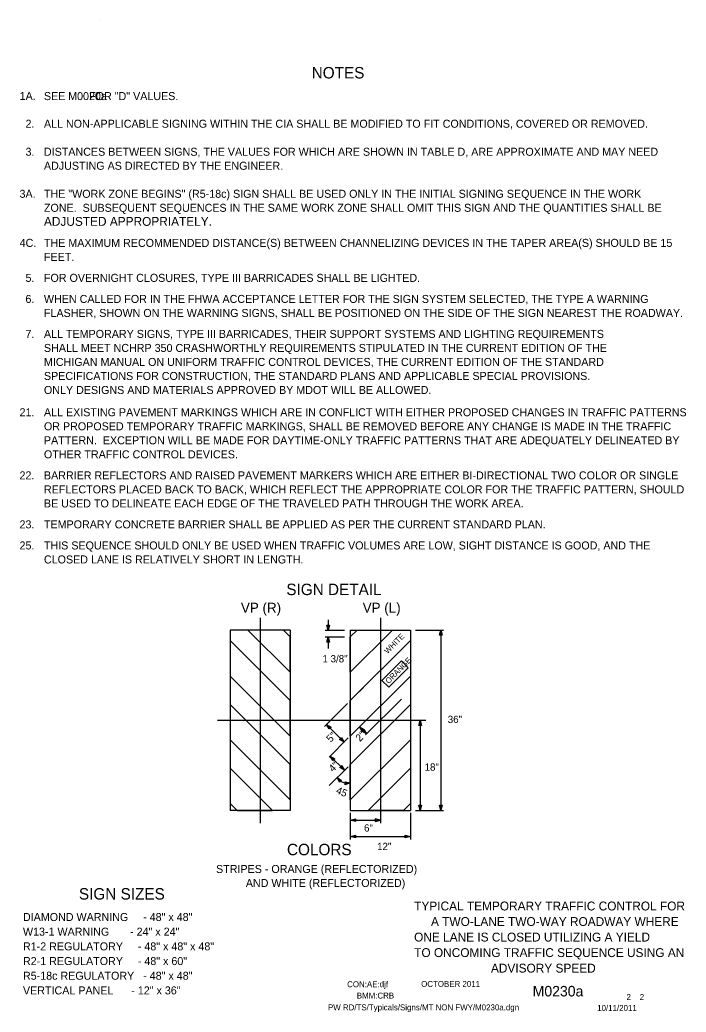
# Model space of a CAD drawing. Extents: x 16768 to 18475, y 7218 to 8259.
# Drawn here: x 17776 to 18475, y 7218 to 8259 of the extents above; entities that cross this region are included whole.
import ezdxf

# ---------------------------------------------------------------- set-up
doc = ezdxf.new("R2010")
doc.units = 0
for name, color, linetype in [('BORDER', 7, 'Continuous'), ('BORDER_SIGNAL_WO', 7, 'Continuous'), ('TRAFFIC_SIGNS_PR', 7, 'Continuous'), ('TYPICAL_TEXT_DIMEN_PR', 7, 'Continuous')]:
    doc.layers.add(name, color=color, linetype=linetype)

msp = doc.modelspace()

# ---------------------------------------------------------------- linework, layer by layer
at = {"layer": 'BORDER'}
msp.add_line((17859.8, 8259.1), (17859.8, 8259.1), dxfattribs=at)
at = {"layer": 'TRAFFIC_SIGNS_PR'}
for p, q in [((18059.9, 7618.8), (17996.9, 7618.8)), ((17996.9, 7618.8), (17996.9, 7429.8)), ((18059.9, 7574.6), (18015.7, 7618.8)), ((18059.9, 7611.7), (18052.8, 7618.8)), ((18059.9, 7618.8), (18059.9, 7429.8)), ((18123, 7618.8), (18186, 7618.8)), ((18123, 7618.8), (18123, 7429.8)), ((18123, 7611.7), (18130.1, 7618.8)), ((18123, 7574.6), (18167.2, 7618.8)), ((18186, 7618.8), (18186, 7429.8)), ((18059.9, 7544.9), (17996.9, 7607.9)), ((18123, 7544.9), (18186, 7607.9)), ((18059.9, 7507.7), (17996.9, 7570.7)), ((18123, 7507.7), (18186, 7570.7)), ((18132.3, 7554.1), (18141.5, 7563.4)), ((18059.9, 7478), (17996.9, 7541)), ((18123, 7478), (18186, 7541)), ((18059.9, 7440.9), (17996.9, 7503.9)), ((18123, 7440.9), (18186, 7503.9)), ((18041.3, 7429.8), (17996.9, 7474.2)), ((18141.6, 7429.8), (18186, 7474.2)), ((18004.2, 7429.8), (17996.9, 7437.1)), ((18178.7, 7429.8), (18186, 7437.1)), ((18059.9, 7429.8), (17996.9, 7429.8)), ((18123, 7429.8), (18186, 7429.8))]:
    msp.add_line(p, q, dxfattribs=at)
for points in [[(18052.8, 7618.8), (18015.7, 7618.8), (18059.9, 7574.6), (18059.9, 7611.7)], [(18130.1, 7618.8), (18167.2, 7618.8), (18123, 7574.6), (18123, 7611.7)], [(18059.9, 7544.9), (17996.9, 7607.9), (17996.9, 7570.7), (18059.9, 7507.7)], [(18123, 7544.9), (18186, 7607.9), (18186, 7570.7), (18123, 7507.7)], [(18059.9, 7478), (17996.9, 7541), (17996.9, 7503.9), (18059.9, 7440.9)], [(18123, 7478), (18186, 7541), (18186, 7503.9), (18123, 7440.9)], [(17996.9, 7474.2), (17996.9, 7437.1), (18004.2, 7429.8), (18041.3, 7429.8)], [(18186, 7474.2), (18186, 7437.1), (18178.7, 7429.8), (18141.6, 7429.8)]]:
    msp.add_lwpolyline(points, close=True, dxfattribs=at)
at = {"layer": 'TYPICAL_TEXT_DIMEN_PR'}
for p, q in [((18028.4, 7631.9), (18028.4, 7416.4)), ((18154.5, 7631.9), (18154.5, 7416.4)), ((18099.9, 7618.8), (18098.4, 7624.2)), ((18098.4, 7624.2), (18099.9, 7624.2)), ((18099.9, 7629.7), (18099.9, 7618.8)), ((18099.9, 7624.2), (18101.3, 7624.2)), ((18101.3, 7624.2), (18099.9, 7618.8)), ((18096.7, 7618.8), (18116.9, 7618.8)), ((18096.7, 7611.7), (18116.9, 7611.7)), ((18098.4, 7606.3), (18099.9, 7611.7)), ((18099.9, 7611.7), (18099.9, 7599.6)), ((18099.9, 7611.7), (18101.3, 7606.3)), ((18191.3, 7618.8), (18220.8, 7618.8)), ((18216.4, 7613.4), (18217.8, 7618.8)), ((18217.8, 7613.4), (18216.4, 7613.4)), ((18217.8, 7618.8), (18217.8, 7429.8)), ((18217.8, 7618.8), (18219.3, 7613.4)), ((18219.3, 7613.4), (18217.8, 7613.4)), ((18099.9, 7606.3), (18098.4, 7606.3)), ((18101.3, 7606.3), (18099.9, 7606.3)), ((18095.9, 7517.7), (18120, 7541.9)), ((18139, 7508.9), (18176.7, 7546.6)), ((17983.8, 7524.3), (18202.2, 7524.3)), ((18116.7, 7501.4), (18098.1, 7520)), ((18100.9, 7515.2), (18098.1, 7520)), ((18098.1, 7520), (18102.9, 7517.2)), ((18101.9, 7516.2), (18100.9, 7515.2)), ((18102.9, 7517.2), (18101.9, 7516.2)), ((18140.1, 7509.9), (18132.6, 7517.4)), ((18135.4, 7512.5), (18132.6, 7517.4)), ((18132.6, 7517.4), (18137.4, 7514.6)), ((18194.7, 7518.9), (18196.2, 7524.3)), ((18196.2, 7518.9), (18194.7, 7518.9)), ((18196.2, 7524.3), (18196.2, 7429.8)), ((18196.2, 7524.3), (18197.6, 7518.9)), ((18197.6, 7518.9), (18196.2, 7518.9)), ((18100.7, 7485.5), (18120.9, 7505.7)), ((18112.9, 7505.2), (18113.9, 7506.3)), ((18113.9, 7506.3), (18116.7, 7501.4)), ((18135.2, 7512.7), (18136.2, 7513.7)), ((18140.1, 7509.9), (18135.2, 7512.7)), ((18136.4, 7513.5), (18135.4, 7512.5)), ((18136.2, 7513.7), (18137.3, 7514.7)), ((18137.4, 7514.6), (18136.4, 7513.5)), ((18137.3, 7514.7), (18140.1, 7509.9)), ((18111.8, 7504.2), (18112.9, 7505.2)), ((18116.7, 7501.4), (18111.8, 7504.2)), ((18116.9, 7471.9), (18102, 7486.8)), ((18104.8, 7482), (18102, 7486.8)), ((18102, 7486.8), (18106.9, 7484)), ((18100.7, 7455.8), (18120.6, 7475.6)), ((18105.8, 7483), (18104.8, 7482)), ((18106.9, 7484), (18105.8, 7483)), ((18112, 7474.7), (18113.1, 7475.7)), ((18116.9, 7471.9), (18112, 7474.7)), ((18113.1, 7475.7), (18114.1, 7476.8)), ((18114.1, 7476.8), (18116.9, 7471.9)), ((18111.6, 7459.2), (18109.2, 7464.2)), ((18109.2, 7464.2), (18113.8, 7461.1)), ((18112.7, 7460.1), (18111.6, 7459.2)), ((18113.8, 7461.1), (18112.7, 7460.1)), ((18117.6, 7458.2), (18117.5, 7459.6)), ((18117.5, 7459.6), (18123, 7458.5)), ((18117.7, 7456.7), (18117.6, 7458.2)), ((18123, 7458.5), (18117.7, 7456.7)), ((18196.2, 7429.8), (18194.7, 7435.2)), ((18194.7, 7435.2), (18196.2, 7435.2)), ((18196.2, 7435.2), (18197.6, 7435.2)), ((18197.6, 7435.2), (18196.2, 7429.8)), ((18217.8, 7429.8), (18216.4, 7435.2)), ((18216.4, 7435.2), (18217.8, 7435.2)), ((18217.8, 7435.2), (18219.3, 7435.2)), ((18219.3, 7435.2), (18217.8, 7429.8)), ((18123, 7427.2), (18123, 7399.2)), ((18186, 7427.2), (18186, 7399.2)), ((18191.3, 7429.8), (18220.8, 7429.8)), ((18123, 7419.6), (18128.4, 7421)), ((18123, 7419.6), (18154.5, 7419.6)), ((18128.4, 7418.1), (18123, 7419.6)), ((18128.4, 7421), (18128.4, 7419.6)), ((18128.4, 7419.6), (18128.4, 7418.1)), ((18154.5, 7419.6), (18149.1, 7421)), ((18149.1, 7421), (18149.1, 7419.6)), ((18149.1, 7419.6), (18149.1, 7418.1)), ((18149.1, 7418.1), (18154.5, 7419.6)), ((18123, 7402.4), (18128.4, 7403.8)), ((18123, 7402.4), (18186, 7402.4)), ((18128.4, 7401), (18123, 7402.4)), ((18128.4, 7403.8), (18128.4, 7402.4)), ((18128.4, 7402.4), (18128.4, 7401)), ((18180.6, 7402.4), (18180.6, 7403.8)), ((18180.6, 7403.8), (18186, 7402.4)), ((18186, 7402.4), (18180.6, 7401)), ((18180.6, 7401), (18180.6, 7402.4))]:
    msp.add_line(p, q, dxfattribs=at)
msp.add_lwpolyline([(18156.1, 7566.1), (18176.6, 7586.5), (18183.7, 7579.3), (18163.3, 7558.9)], close=True, dxfattribs=at)
msp.add_arc((18120.2, 7471.4), 13.1, 212.8393, 282.1565, dxfattribs=at)

# ---------------------------------------------------------------- texts
at = {"layer": 'BORDER'}
for s, p in [('TYPICAL TEMPORARY TRAFFIC CONTROL FOR', (18190, 7324.8)), ('A TWO-LANE TWO-WAY ROADWAY WHERE', (18207.6, 7308.5)), ('ONE LANE IS CLOSED UTILIZING A YIELD ', (18189.9, 7292.2)), ('TO ONCOMING TRAFFIC SEQUENCE USING AN', (18190, 7275.9)), ('ADVISORY SPEED', (18270.5, 7259.6))]:
    msp.add_text(s, height=9.3, dxfattribs=at).set_placement(p)
at = {"layer": 'BORDER_SIGNAL_WO'}
for s, height, p in [('CON:AE:djf', 6.2, (18119.7, 7244.3)), ('    OCTOBER 2011    ', 6.2, (18188.1, 7244.6)), ('    M0230a    ', 11, (18297.9, 7234.6)), ('BMM:CRB   ', 6.2, (18129.8, 7232.4)), (' 2    2 ', 6.2, (18410.4, 7230.9)), ('PW RD/TS/Typicals/Signs/MT NON FWY/M0230a.dgn     ', 6.2, (18099.6, 7220)), ('10/11/2011    ', 6.2, (18381.9, 7219.4))]:
    msp.add_text(s, height=height, dxfattribs=at).set_placement(p)
at = {"layer": 'TYPICAL_TEXT_DIMEN_PR'}
for s, height, p in [('NOTES', 12, (18082.5, 8197.6)), ('1A.', 8.4, (17776.2, 8175)), ('SEE        FOR "D" VALUES.', 8.4, (17801.7, 8174.9)), ('M0020a', 8.4, (17827.1, 8174.9)), ('2.', 8.4, (17782.4, 8145.9)), ('ALL NON-APPLICABLE SIGNING WITHIN THE CIA SHALL BE MODIFIED TO FIT CONDITIONS, COVERED OR REMOVED.', 8.4, (17801.7, 8145.9)), ('3.', 8.4, (17782.4, 8116.5)), ('DISTANCES BETWEEN SIGNS, THE VALUES FOR WHICH ARE SHOWN IN TABLE D, ARE APPROXIMATE AND MAY NEED', 8.4, (17801.7, 8116.5)), ('ADJUSTING AS DIRECTED BY THE ENGINEER.', 8.4, (17801.7, 8101.8)), ('3A.', 8.4, (17776.1, 8072.4)), ('THE "WORK ZONE BEGINS" (R5-18c) SIGN SHALL BE USED ONLY IN THE INITIAL SIGNING SEQUENCE IN THE WORK', 8.4, (17801.7, 8072.4)), ('ZONE.  SUBSEQUENT SEQUENCES IN THE SAME WORK ZONE SHALL OMIT THIS SIGN AND THE QUANTITIES SHALL BE', 8.4, (17801.7, 8057.7)), ('ADJUSTED APPROPRIATELY.', 9.3, (17801.7, 8043)), ('4C.', 8.4, (17776.2, 8020.9)), ('THE MAXIMUM RECOMMENDED DISTANCE(S) BETWEEN CHANNELIZING DEVICES IN THE TAPER AREA(S) SHOULD BE 15', 8.4, (17801.7, 8020.9)), ('FEET.', 8.4, (17801.7, 8006.2)), ('5.', 8.4, (17782.4, 7984.2)), ('FOR OVERNIGHT CLOSURES, TYPE III BARRICADES SHALL BE LIGHTED.', 8.4, (17801.7, 7984.2)), ('6.', 8.4, (17782.3, 7962.1)), ('WHEN CALLED FOR IN THE FHWA ACCEPTANCE LETTER FOR THE SIGN SYSTEM SELECTED, THE TYPE A WARNING ', 8.4, (17801.7, 7962.1)), ('FLASHER, SHOWN ON THE WARNING SIGNS, SHALL BE POSITIONED ON THE SIDE OF THE SIGN NEAREST THE ROADWAY.', 8.4, (17801.7, 7947.4)), ('7.', 8.4, (17782.3, 7925.4)), ('ALL TEMPORARY SIGNS, TYPE III BARRICADES, THEIR SUPPORT SYSTEMS AND LIGHTING REQUIREMENTS', 8.4, (17801.7, 7925.4)), ('SHALL MEET NCHRP 350 CRASHWORTHLY REQUIREMENTS STIPULATED IN THE CURRENT EDITION OF THE', 8.4, (17801.7, 7910.7)), ('MICHIGAN MANUAL ON UNIFORM TRAFFIC CONTROL DEVICES, THE CURRENT EDITION OF THE STANDARD', 8.4, (17801.7, 7896)), ('SPECIFICATIONS FOR CONSTRUCTION, THE STANDARD PLANS AND APPLICABLE SPECIAL PROVISIONS.', 8.4, (17801.7, 7881.3)), ('ONLY DESIGNS AND MATERIALS APPROVED BY MDOT WILL BE ALLOWED.', 8.4, (17801.7, 7866.6)), ('21.', 8.4, (17776.1, 7843.2)), ('ALL EXISTING PAVEMENT MARKINGS WHICH ARE IN CONFLICT WITH EITHER PROPOSED CHANGES IN TRAFFIC PATTERNS', 8.4, (17801.7, 7843.2)), ('OR PROPOSED TEMPORARY TRAFFIC MARKINGS, SHALL BE REMOVED BEFORE ANY CHANGE IS MADE IN THE TRAFFIC', 8.4, (17801.7, 7828.5)), ('PATTERN.  EXCEPTION WILL BE MADE FOR DAYTIME-ONLY TRAFFIC PATTERNS THAT ARE ADEQUATELY DELINEATED BY', 8.4, (17801.7, 7813.8)), ('OTHER TRAFFIC CONTROL DEVICES.', 8.4, (17801.7, 7799.1)), ('22.', 8.4, (17776.1, 7777)), ('BARRIER REFLECTORS AND RAISED PAVEMENT MARKERS WHICH ARE EITHER BI-DIRECTIONAL TWO COLOR OR SINGLE', 8.4, (17801.7, 7777)), ('REFLECTORS PLACED BACK TO BACK, WHICH REFLECT THE APPROPRIATE COLOR FOR THE TRAFFIC PATTERN, SHOULD', 8.4, (17801.7, 7762.3)), ('BE USED TO DELINEATE EACH EDGE OF THE TRAVELED PATH THROUGH THE WORK AREA.', 8.4, (17801.7, 7747.6)), ('23.', 8.4, (17776.1, 7725.6)), ('TEMPORARY CONCRETE BARRIER SHALL BE APPLIED AS PER THE CURRENT STANDARD PLAN.', 8.4, (17801.7, 7725.6)), ('25.', 8.4, (17776.1, 7703.5)), ('THIS SEQUENCE SHOULD ONLY BE USED WHEN TRAFFIC VOLUMES ARE LOW, SIGHT DISTANCE IS GOOD, AND THE', 8.4, (17801.7, 7703.5)), ('CLOSED LANE IS RELATIVELY SHORT IN LENGTH.', 8.4, (17801.7, 7688.8)), ('SIGN DETAIL', 12, (18055.9, 7655.6)), ('VP (R)', 10.5, (18008.3, 7637.1)), ('VP (L)', 10.5, (18136, 7637.1)), ('1 3/8"', 7.65, (18093.8, 7585)), ('36"', 7.65, (18225.2, 7521.4)), ('18"', 7.65, (18200.9, 7471.4)), ('6"', 7.65, (18137.4, 7407.5)), ('COLORS', 12, (18056.6, 7382.7)), ('12"', 7.65, (18151.1, 7388.1)), ('STRIPES - ORANGE (REFLECTORIZED)', 8.4, (17982.2, 7364.1)), ('          AND WHITE (REFLECTORIZED)', 8.4, (17982.2, 7349.4)), ('SIGN SIZES', 12, (17838.4, 7336.2)), ('DIAMOND WARNING     - 48" x 48"', 8.4, (17779.7, 7313.7)), ('W13-1 WARNING       - 24" x 24"', 8.4, (17779.7, 7298.3)), ('R1-2 REGULATORY     - 48" x 48" x 48"', 8.4, (17779.7, 7282.9)), ('R2-1 REGULATORY     - 48" x 60"', 8.4, (17779.7, 7267.5)), ('R5-18c REGULATORY   - 48" x 48"', 8.4, (17779.7, 7252.1)), ('VERTICAL PANEL      - 12" x 36"', 8.4, (17779.7, 7236.7))]:
    msp.add_text(s, height=height, dxfattribs=at).set_placement(p)
for s, height, rotation, p in [('WHITE', 6, 45, (18162.2, 7593.5)), ('ORANGE', 6, 45, (18163.2, 7562.1)), ('5"', 7.65, 45, (18102.4, 7500.6)), ('2"', 7.65, 45.0095, (18133.1, 7501.4)), ('4"', 7.65, 45, (18104.8, 7469.5)), ('45', 7.65, 337.5007, (18107.3, 7447.9))]:
    msp.add_text(s, height=height, rotation=rotation, dxfattribs=at).set_placement(p)

doc.saveas('drawing.dxf')
